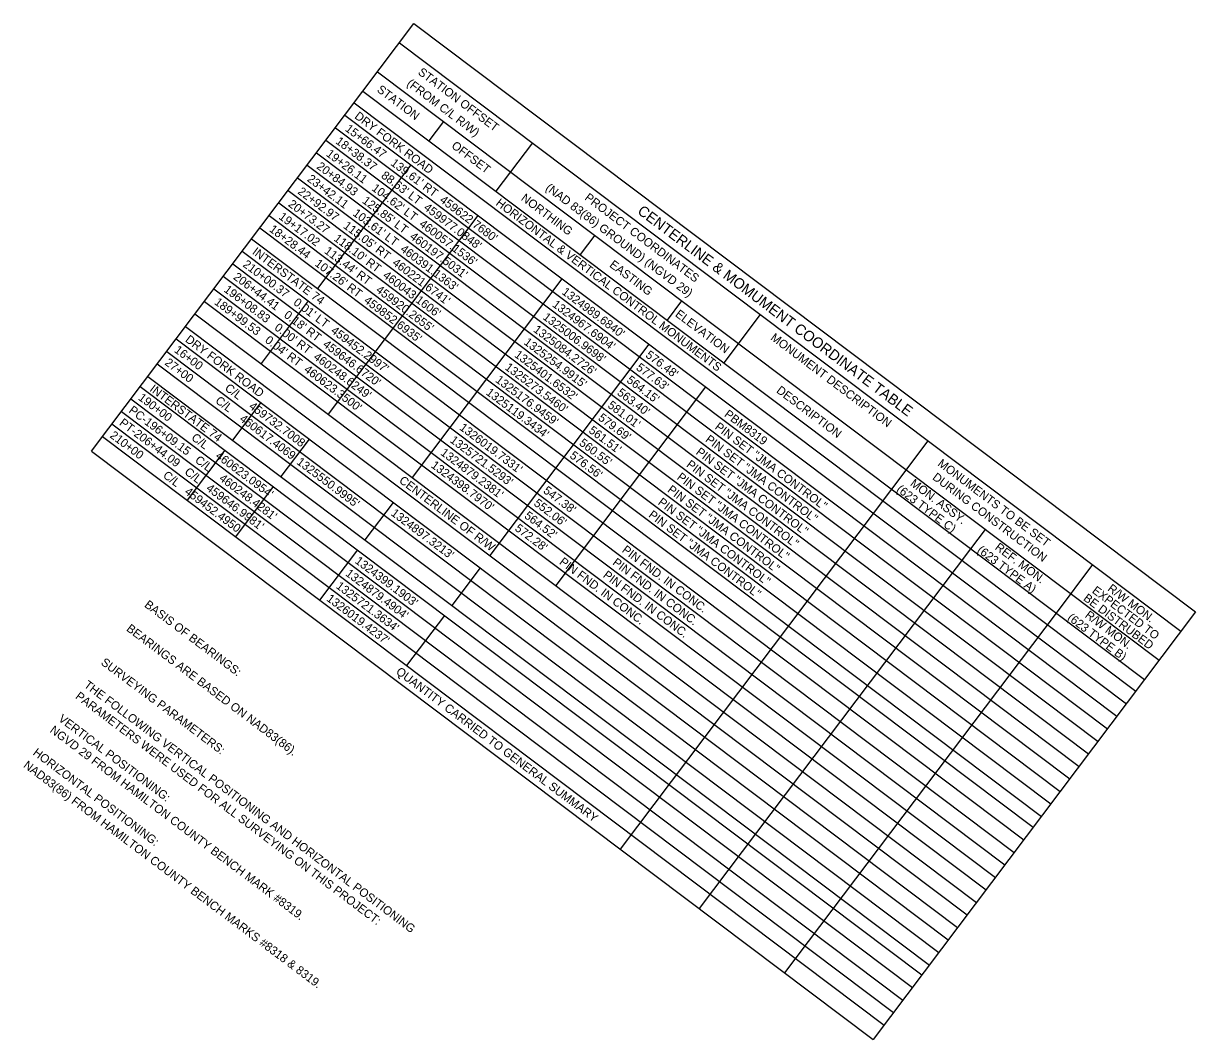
# Model space of a CAD drawing. Extents: x 1323137 to 1326838, y 458936 to 461644.
# Drawn here: x 1325031.8 to 1325418.8, y 459092.5 to 459428.3 of the extents above; entities that cross this region are included whole.
import ezdxf

# ---------------------------------------------------------------- set-up
doc = ezdxf.new("R2010")
doc.units = 0
doc.layers.add('SG_P_Poles', color=7, linetype='Continuous')

msp = doc.modelspace()

# ---------------------------------------------------------------- linework, layer by layer
at = {"layer": 'SG_P_Poles'}
for p, q in [((1325054.28, 459287), (1325160.75, 459428.29)), ((1325160.75, 459428.29), (1325418.84, 459233.81)), ((1325155.93, 459421.9), (1325414.02, 459227.42)), ((1325148.71, 459412.32), (1325406.8, 459217.84)), ((1325143.9, 459405.93), (1325401.98, 459211.45)), ((1325141.01, 459402.1), (1325399.1, 459207.62)), ((1325137.89, 459397.96), (1325395.98, 459203.48)), ((1325170.51, 459395.89), (1325165.7, 459389.5)), ((1325134.78, 459393.82), (1325392.86, 459199.34)), ((1325131.66, 459389.69), (1325389.74, 459195.2)), ((1325199.86, 459388.81), (1325187.82, 459372.83)), ((1325128.54, 459385.55), (1325386.63, 459191.07)), ((1325125.42, 459381.41), (1325383.51, 459186.93)), ((1325159.69, 459381.53), (1325128.94, 459340.72)), ((1325122.31, 459377.28), (1325380.39, 459182.79)), ((1325119.19, 459373.14), (1325377.27, 459178.66)), ((1325116.07, 459369), (1325374.16, 459174.52)), ((1325112.95, 459364.87), (1325371.04, 459170.38)), ((1325181.82, 459364.86), (1325132.36, 459299.23)), ((1325109.84, 459360.73), (1325367.92, 459166.25)), ((1325107.14, 459357.15), (1325365.22, 459162.66)), ((1325220.42, 459358.29), (1325215.6, 459351.9)), ((1325104.02, 459353.01), (1325362.11, 459158.53)), ((1325100.9, 459348.87), (1325358.99, 459154.39)), ((1325097.78, 459344.74), (1325355.87, 459150.25)), ((1325094.67, 459340.6), (1325352.75, 459146.12)), ((1325209.6, 459343.93), (1325160.13, 459278.29)), ((1325125.82, 459336.58), (1325110.23, 459315.9)), ((1325249.14, 459336.64), (1325244.33, 459330.25)), ((1325091.55, 459336.46), (1325349.64, 459141.98)), ((1325088.43, 459332.32), (1325346.52, 459137.84)), ((1325275.08, 459332.12), (1325263.05, 459316.15)), ((1325085.31, 459328.19), (1325343.4, 459133.71)), ((1325082.2, 459324.05), (1325340.28, 459129.57)), ((1325238.32, 459322.28), (1325185.74, 459252.51)), ((1325079.08, 459319.91), (1325337.17, 459125.43)), ((1325075.96, 459315.78), (1325334.05, 459121.29)), ((1325072.85, 459311.64), (1325330.93, 459117.16)), ((1325070.36, 459308.34), (1325328.45, 459113.86)), ((1325257.04, 459308.18), (1325207.58, 459242.54)), ((1325067.24, 459304.21), (1325325.33, 459109.73)), ((1325110.14, 459302.99), (1325100.79, 459290.58)), ((1325064.13, 459300.07), (1325322.21, 459105.59)), ((1325061.01, 459295.93), (1325319.1, 459101.45)), ((1325057.89, 459291.8), (1325315.98, 459097.31)), ((1325126.12, 459290.95), (1325116.77, 459278.54)), ((1325330.45, 459290.39), (1325318.42, 459274.42)), ((1325054.28, 459287), (1325312.37, 459092.52)), ((1325098.3, 459287.29), (1325085.84, 459270.74)), ((1325114.28, 459275.25), (1325101.82, 459258.7)), ((1325318.42, 459274.42), (1325228.8, 459155.49)), ((1325153.9, 459270.02), (1325144.55, 459257.61)), ((1325349.37, 459261.12), (1325344.55, 459254.73)), ((1325142.06, 459254.31), (1325129.59, 459237.76)), ((1325344.55, 459254.73), (1325254.94, 459135.8)), ((1325182.63, 459248.37), (1325173.27, 459235.96)), ((1325384.79, 459249.45), (1325372.76, 459233.47)), ((1325170.79, 459232.66), (1325158.32, 459216.12)), ((1325372.76, 459233.47), (1325283.14, 459114.55)), ((1325418.84, 459233.81), (1325312.37, 459092.52))]:
    msp.add_line(p, q, dxfattribs=at)

# ---------------------------------------------------------------- texts
for s, height, p in [('STATION OFFSET', 2.8, (1325161.85, 459411.69)), ('STATION', 2.8, (1325148.29, 459405.94)), ('(FROM C/L R/W)', 2.8, (1325158.14, 459407.98)), ('DRY FORK ROAD', 2.8, (1325140.9, 459397.16)), ("15+66.47   139.61' RT  459622.7680'", 2.8, (1325137.77, 459393.01)), ("18+38.37   88.63' LT  459977.0848'", 2.8, (1325134.64, 459388.86)), ('OFFSET', 2.8, (1325172.89, 459387.4)), ("19+26.11   104.62' LT  460057.1536'", 2.8, (1325131.51, 459384.7)), ("20+84.93   125.85' LT  460197.5031'", 2.8, (1325128.38, 459380.55)), ("23+42.11   103.61' LT  460391.1363'", 2.8, (1325125.25, 459376.4)), ('(NAD 83(86) GROUND) (NGVD 29)', 2.8, (1325203.94, 459373.46)), ("22+92.97   115.05' RT  460221.6741'", 2.8, (1325122.12, 459372.25)), ('NORTHING', 2.8, (1325195.87, 459370.08)), ('PROJECT COORDINATES', 2.8, (1325216.87, 459370.23)), ("20+73.27   118.10' RT  460043.1606'", 2.8, (1325118.99, 459368.09)), ('HORIZONTAL & VERTICAL CONTROL MONUMENTS', 2.8, (1325187.55, 459368.46)), ('CENTERLINE & MOMUMENT COORDINATE TABLE', 3.5, (1325234.27, 459365.7)), ("19+17.02   113.44' RT   459920.2655'", 2.8, (1325115.86, 459363.94)), ("18+28.44   107.26' RT  459852.6935'", 2.8, (1325112.73, 459359.79)), ('INTERSTATE 74', 2.8, (1325107.12, 459352.33)), ("210+00.37   0.01' LT  459452.2997'", 2.8, (1325103.99, 459348.18)), ('EASTING', 2.8, (1325225.07, 459348.07)), ("206+44.41   0.18' RT  459646.6720'", 2.8, (1325100.86, 459344.03)), ("196+08.83   0.00' RT  460248.6249'", 2.8, (1325097.73, 459339.87)), ("1324989.6840'", 2.8, (1325209.33, 459339.09)), ("189+99.53   0.04' RT  460623.3500'", 2.8, (1325094.6, 459335.72)), ("1324967.6904'", 2.8, (1325206.2, 459334.93)), ('ELEVATION', 2.8, (1325246.77, 459331.73)), ("1325006.9698'", 2.8, (1325203.07, 459330.78)), ('DRY FORK ROAD', 2.8, (1325084.98, 459323.35)), ("1325084.2726'", 2.8, (1325199.94, 459326.63)), ('MONUMENT DESCRIPTION', 2.8, (1325278.27, 459323.97)), ("16+00          C/L    459732.7008'", 2.8, (1325081.35, 459319.89)), ("1325254.9915'", 2.8, (1325196.81, 459322.48)), ("27+00          C/L    460617.4069' 1325550.9995'", 2.8, (1325078.22, 459315.73)), ("1325401.6532'", 2.8, (1325193.68, 459318.32)), (" 576.48'", 2.8, (1325236.16, 459318.87)), ("1325273.5460'", 2.8, (1325190.55, 459314.17)), (" 577.63'", 2.8, (1325233.03, 459314.71)), ("1325176.9459'", 2.8, (1325187.42, 459310.02)), (" 564.15'", 2.8, (1325229.9, 459310.56)), ("190+00         C/L    460623.0954'", 2.8, (1325069.47, 459304.13)), ('INTERSTATE 74', 2.8, (1325073.25, 459307)), ("1325119.3434'", 2.8, (1325184.29, 459305.86)), (" 563.40'", 2.8, (1325226.77, 459306.41)), ('DESCRIPTION', 2.8, (1325280.19, 459306.54)), ("PC-196+09.15   C/L    460248.4281'", 2.8, (1325066.34, 459299.97)), (" 581.01'", 2.8, (1325223.64, 459302.26)), ("PT-206+44.09   C/L   459646.9981'", 2.8, (1325063.21, 459295.82)), (" 579.69'", 2.8, (1325220.51, 459298.1)), ('PBM8319', 2.8, (1325262.99, 459298.65)), ("1326019.7331'", 2.8, (1325175.54, 459294.26)), (" 561.51'", 2.8, (1325217.38, 459293.95)), ('PIN SET "JMA CONTROL"', 2.8, (1325259.86, 459294.49)), ("210+00         C/L   459452.4950'", 2.8, (1325060.09, 459291.67)), ("1325721.5293'", 2.8, (1325172.41, 459290.1)), (" 560.55'", 2.8, (1325214.25, 459289.8)), ('PIN SET "JMA CONTROL"', 2.8, (1325256.73, 459290.34)), ("1324879.2381'", 2.8, (1325169.28, 459285.95)), (" 576.56'", 2.8, (1325211.12, 459285.64)), ('PIN SET "JMA CONTROL"', 2.8, (1325253.61, 459286.19)), ("1324398.7970'", 2.8, (1325166.16, 459281.8)), ('PIN SET "JMA CONTROL"', 2.8, (1325250.48, 459282.03)), ('MONUMENTS TO BE SET ', 2.8, (1325333.46, 459282.37)), ('CENTERLINE OF R/W', 2.8, (1325155.6, 459276.77)), ('PIN SET "JMA CONTROL"', 2.8, (1325247.35, 459277.88)), ('DURING CONSTRUCTION', 2.8, (1325331.72, 459277.84)), (" 547.38'", 2.8, (1325202.38, 459274.04)), ('PIN SET "JMA CONTROL"', 2.8, (1325244.22, 459273.73)), ('(623 TYPE C)', 2.8, (1325319.84, 459273.86)), ('MON. ASSY.', 2.8, (1325324.38, 459275.79)), (" 552.06'", 2.8, (1325199.25, 459269.88)), ('PIN SET "JMA CONTROL"', 2.8, (1325241.09, 459269.58)), ("1324897.3213'", 2.8, (1325152.91, 459265.96)), (" 564.52'", 2.8, (1325196.12, 459265.73)), ('PIN SET "JMA CONTROL"', 2.8, (1325237.96, 459265.42)), (" 572.28'      PIN FND. IN CONC.", 2.8, (1325192.99, 459261.58)), ('PIN FND. IN CONC.', 2.8, (1325229.21, 459253.82)), ('(623 TYPE A)', 2.8, (1325346.49, 459253.78)), ('REF. MON.', 2.8, (1325352.36, 459254.7)), ("1324399.1903'", 2.8, (1325141.03, 459250.2)), ('PIN FND. IN CONC.', 2.8, (1325226.08, 459249.66)), ("1324879.4904'", 2.8, (1325137.9, 459246.05)), ('PIN FND. IN CONC.', 2.8, (1325222.95, 459245.51)), ("1325721.3634'", 2.8, (1325134.77, 459241.9)), ('BE DISTRUBED', 2.8, (1325381.55, 459237.88)), ('EXPECTED TO ', 2.8, (1325384.44, 459240.38)), ('R/W MON. ', 2.8, (1325389.55, 459241.07)), ('BASIS OF BEARINGS:', 2.8, (1325071.5, 459235.71)), ("1326019.4237'", 2.8, (1325131.64, 459237.74)), ('(623 TYPE B)', 2.8, (1325376.29, 459231.43)), ('R/W MON.', 2.8, (1325382.09, 459232.26)), ('BEARINGS ARE BASED ON NAD83(86).', 2.8, (1325065.56, 459227.83)), ('SURVEYING PARAMETERS:', 2.8, (1325057.14, 459216.65)), ('QUANTITY CARRIED TO GENERAL SUMMARY', 2.8, (1325154.57, 459213.6)), ('THE FOLLOWING VERTICAL POSITIONING AND HORIZONTAL POSITIONING ', 2.8, (1325051.52, 459209.19)), ('PARAMETERS WERE USED FOR ALL SURVEYING ON THIS PROJECT:', 2.8, (1325048.71, 459205.46)), ('VERTICAL POSITIONING:', 2.8, (1325043.09, 459198.01)), ('NGVD 29 FROM HAMILTON COUNTY BENCH MARK #8319.', 2.8, (1325040.29, 459194.28)), ('HORIZONTAL POSITIONING:', 2.8, (1325034.67, 459186.83)), ('NAD83(86) FROM HAMILTON COUNTY BENCH MARKS #8318 & 8319.', 2.8, (1325031.54, 459182.68))]:
    msp.add_text(s, height=height, rotation=323, dxfattribs=at).set_placement(p)

doc.saveas('drawing.dxf')
